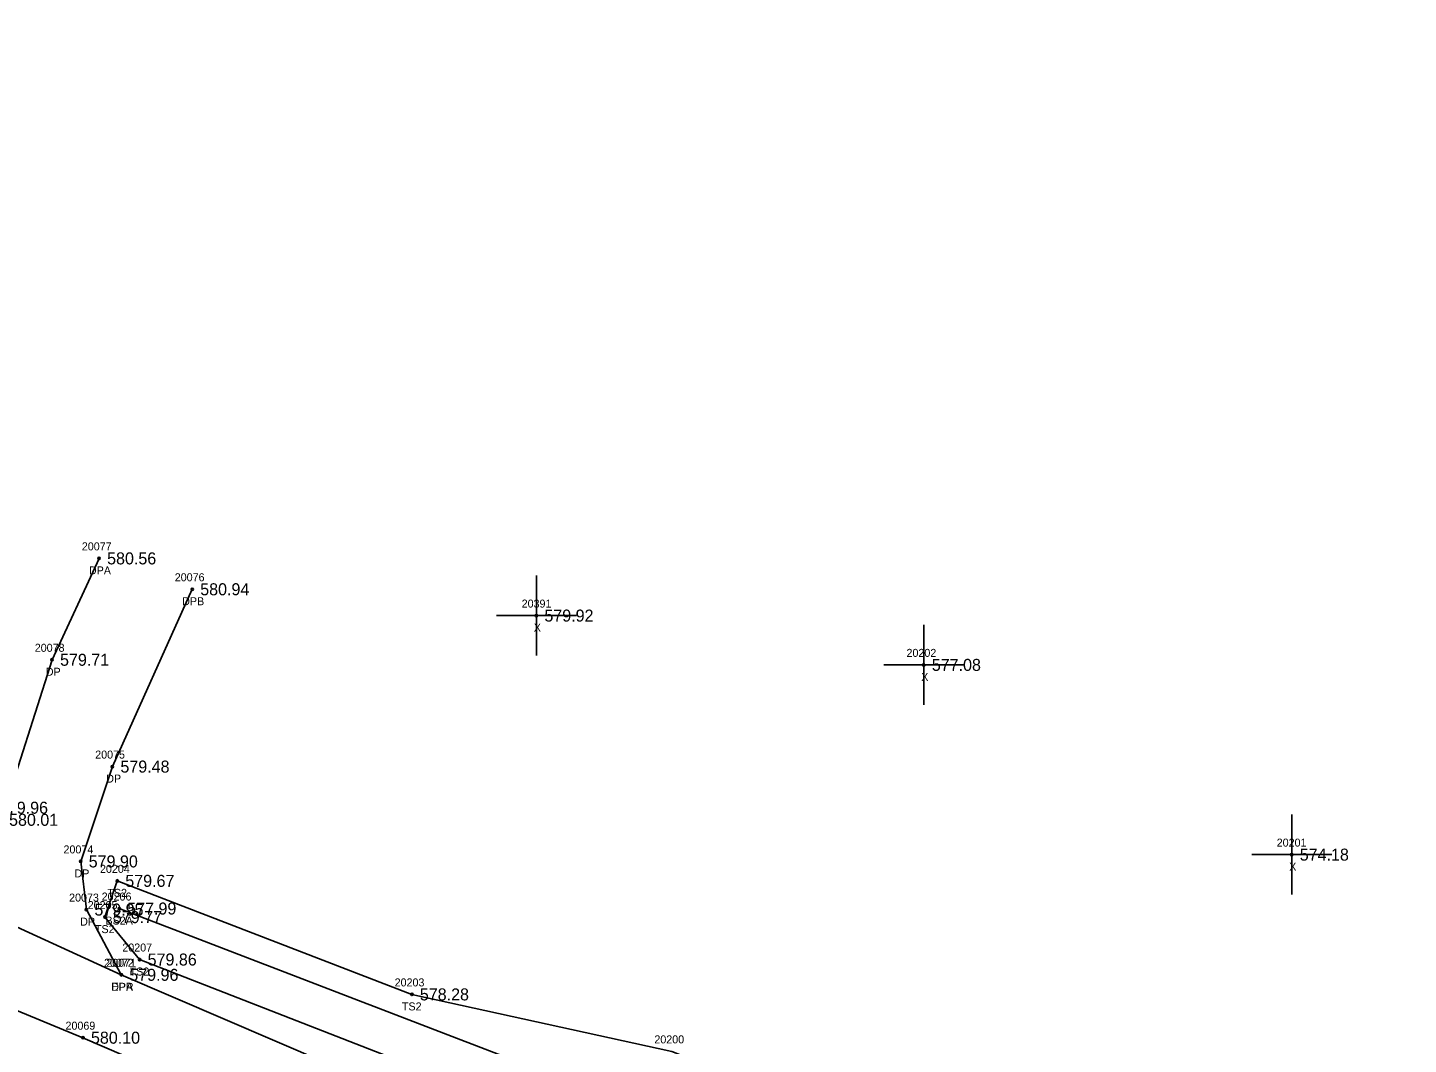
# Model space of a CAD drawing. Extents: x 1664837 to 1666270, y 987403 to 988245.
# Drawn here: x 1665140.5 to 1665313, y 987916.7 to 988043.8 of the extents above; entities that cross this region are included whole.
import ezdxf

# ---------------------------------------------------------------- set-up
doc = ezdxf.new("R2010")
doc.units = 0
for name, color, linetype in [('RD_DTM_BkLn1', 7, 'Continuous'), ('RD_DTM_BkLn2', 7, 'Continuous'), ('RD_DTM_BkLn_txCode', 7, 'Continuous'), ('RD_EX_Driveway', 7, 'Continuous'), ('RD_EX_Driveway_txCode', 7, 'Continuous'), ('RD_EX_Misc', 7, 'Continuous'), ('RD_EX_Misc_txCode', 7, 'Continuous'), ('RD_EX_Road', 7, 'Continuous'), ('RD_EX_Road_txCode', 7, 'Continuous'), ('RD_EX_TX_Driveway_ELEV', 7, 'Continuous'), ('RD_EX_TX_Misc_ELEV', 7, 'Continuous'), ('RD_EX_TX_Road_ELEV', 7, 'Continuous'), ('RD_HC_Survey_ELEV', 7, 'Continuous'), ('RD_HC_Survey_txCode', 7, 'Continuous'), ('RD_SMD_Locator', 7, 'Continuous')]:
    doc.layers.add(name, color=color, linetype=linetype)

msp = doc.modelspace()

# ---------------------------------------------------------------- linework, layer by layer
at = {"layer": 'RD_DTM_BkLn1'}
msp.add_lwpolyline([(1665502.18, 987767.43), (1665469.18, 987781.68), (1665423.29, 987801.23), (1665377.17, 987820.37), (1665331.28, 987839.54), (1665285.44, 987859.03), (1665239.3, 987878.58), (1665193.14, 987897.86), (1665147.41, 987917.57), (1665101.07, 987936.7), (1665055.19, 987956.08), (1665009.23, 987975.83), (1664963.42, 987995.66), (1664917.15, 988015.07), (1664871.41, 988034.69)], dxfattribs=at)
at = {"layer": 'RD_DTM_BkLn2'}
for points in [[(1665526.5, 987797.57), (1665466.88, 987821.13), (1665430.93, 987834.67), (1665385.41, 987852.45), (1665344.34, 987868.11), (1665298.9, 987885.03), (1665253.91, 987902.76), (1665220.99, 987915.86), (1665188.5, 987922.98), (1665151.7, 987937.17), (1665150.15, 987932.64), (1665154.49, 987927.34), (1665198.68, 987910.11), (1665245.58, 987892.26), (1665291.48, 987872.02), (1665339.41, 987857.06), (1665385.96, 987838.24), (1665430.55, 987820.66), (1665476.41, 987799.7), (1665510.35, 987785.06), (1665506.66, 987778.89)], [(1665151.94, 987933.71), (1665201.46, 987914.66), (1665247.51, 987895.52), (1665294.62, 987876.98), (1665342.05, 987862.7), (1665388.78, 987843.93), (1665435.12, 987827.47), (1665481.62, 987807.44), (1665516.85, 987790.52)]]:
    msp.add_lwpolyline(points, dxfattribs=at)
at = {"layer": 'RD_EX_Driveway'}
for points in [[(1665149.43, 987977.47), (1665143.55, 987964.8), (1665137.18, 987944.8), (1665133.32, 987939.05), (1665127.55, 987936.7)], [(1665152.2, 987925.43), (1665147.84, 987933.58), (1665147.13, 987939.6), (1665151.09, 987951.45), (1665161.06, 987973.61)]]:
    msp.add_lwpolyline(points, dxfattribs=at)
at = {"layer": 'RD_EX_Misc'}
for p, q in [((1665204.06, 987965.32), (1665204.06, 987975.32)), ((1665199.06, 987970.32), (1665209.06, 987970.32)), ((1665252.46, 987959.16), (1665252.46, 987969.16)), ((1665247.46, 987964.16), (1665257.46, 987964.16)), ((1665298.43, 987935.45), (1665298.43, 987945.45)), ((1665293.43, 987940.45), (1665303.43, 987940.45))]:
    msp.add_line(p, q, dxfattribs=at)
at = {"layer": 'RD_EX_Road'}
msp.add_lwpolyline([(1665506.06, 987776.52), (1665471.95, 987789.57), (1665426.52, 987809.19), (1665380.33, 987828.78), (1665335.61, 987847.53), (1665288.25, 987866.82), (1665242.34, 987886.56), (1665197.07, 987906.16), (1665152.2, 987925.43), (1665127.55, 987936.7), (1665104.5, 987945.2), (1665059.19, 987965.3), (1665013.63, 987984.66), (1664966.38, 988005.06), (1664921.66, 988023.83), (1664875.55, 988043.8)], dxfattribs=at)
at = {"layer": 'RD_SMD_Locator'}
for centre in [(1665149.43, 987977.47), (1665161.06, 987973.61), (1665204.06, 987970.32), (1665143.55, 987964.8), (1665252.46, 987964.16), (1665151.09, 987951.45), (1665298.43, 987940.45), (1665147.13, 987939.6), (1665151.7, 987937.17), (1665147.84, 987933.58), (1665151.94, 987933.71), (1665150.15, 987932.64), (1665154.49, 987927.34), (1665152.2, 987925.43), (1665152.2, 987925.43), (1665188.5, 987922.98), (1665147.41, 987917.57)]:
    msp.add_circle(centre, 0.15, dxfattribs=at)

# ---------------------------------------------------------------- texts
at = {"layer": 'RD_DTM_BkLn_txCode'}
for s, p in [('20204', (1665149.54, 987938.17)), ('20206', (1665149.75, 987934.71)), ('TS2', (1665150.46, 987935.17)), ('20205', (1665148, 987933.64)), ('TS2', (1665148.91, 987930.64)), ('BS2A', (1665150.22, 987931.71)), ('20207', (1665152.33, 987928.34)), ('TS2', (1665153.24, 987925.34)), ('20203', (1665186.35, 987923.98)), ('TS2', (1665187.26, 987920.98)), ('20200', (1665218.8, 987916.86))]:
    msp.add_text(s, height=1, dxfattribs=at).set_placement(p)
at = {"layer": 'RD_EX_Driveway_txCode'}
for s, p in [('20077', (1665147.27, 987978.47)), ('DPA', (1665148.16, 987975.47)), ('20076', (1665158.88, 987974.61)), ('DPB', (1665159.81, 987971.61)), ('20078', (1665141.39, 987965.8)), ('DP', (1665142.77, 987962.8)), ('20075', (1665148.94, 987952.45)), ('DP', (1665150.32, 987949.45)), ('20074', (1665144.98, 987940.6)), ('DP', (1665146.35, 987937.6)), ('20073', (1665145.68, 987934.58)), ('DP', (1665147.06, 987931.58)), ('20072', (1665150.04, 987926.43)), ('DPA', (1665150.93, 987923.43))]:
    msp.add_text(s, height=1, dxfattribs=at).set_placement(p)
at = {"layer": 'RD_EX_Misc_txCode'}
for s, p in [('20391', (1665202.22, 987971.32)), ('X', (1665203.74, 987968.32)), ('20202', (1665250.3, 987965.16)), ('X', (1665252.14, 987962.16)), ('20201', (1665296.55, 987941.45)), ('X', (1665298.11, 987938.45))]:
    msp.add_text(s, height=1, dxfattribs=at).set_placement(p)
at = {"layer": 'RD_EX_Road_txCode'}
for s, p in [('20071', (1665150.33, 987926.43)), ('EPR', (1665150.97, 987923.43))]:
    msp.add_text(s, height=1, dxfattribs=at).set_placement(p)
at = {"layer": 'RD_EX_TX_Driveway_ELEV'}
for s, p in [('580.56', (1665150.43, 987976.72)), ('580.94', (1665162.06, 987972.86)), ('579.71', (1665144.55, 987964.05)), ('579.48', (1665152.09, 987950.7)), ('580.01', (1665138.18, 987944.05)), ('579.90', (1665148.13, 987938.85)), ('579.95', (1665148.84, 987932.83)), ('579.96', (1665153.2, 987924.68))]:
    msp.add_text(s, height=1.5, dxfattribs=at).set_placement(p)
at = {"layer": 'RD_EX_TX_Misc_ELEV'}
for s, p in [('579.92', (1665205.06, 987969.57)), ('577.08', (1665253.46, 987963.41)), ('579.96', (1665136.91, 987945.56)), ('574.18', (1665299.43, 987939.7)), ('579.67', (1665152.7, 987936.42)), ('579.77', (1665151.15, 987931.89)), ('577.99', (1665152.94, 987932.96)), ('579.86', (1665155.49, 987926.59)), ('578.28', (1665189.5, 987922.23))]:
    msp.add_text(s, height=1.5, dxfattribs=at).set_placement(p)
at = {"layer": 'RD_EX_TX_Road_ELEV'}
msp.add_text('579.96', height=1.5, dxfattribs=at).set_placement((1665153.2, 987924.68))
at = {"layer": 'RD_HC_Survey_ELEV'}
msp.add_text('580.10', height=1.5, dxfattribs=at).set_placement((1665148.41, 987916.82))
at = {"layer": 'RD_HC_Survey_txCode'}
msp.add_text('20069', height=1, dxfattribs=at).set_placement((1665145.23, 987918.57))

doc.saveas('drawing.dxf')
